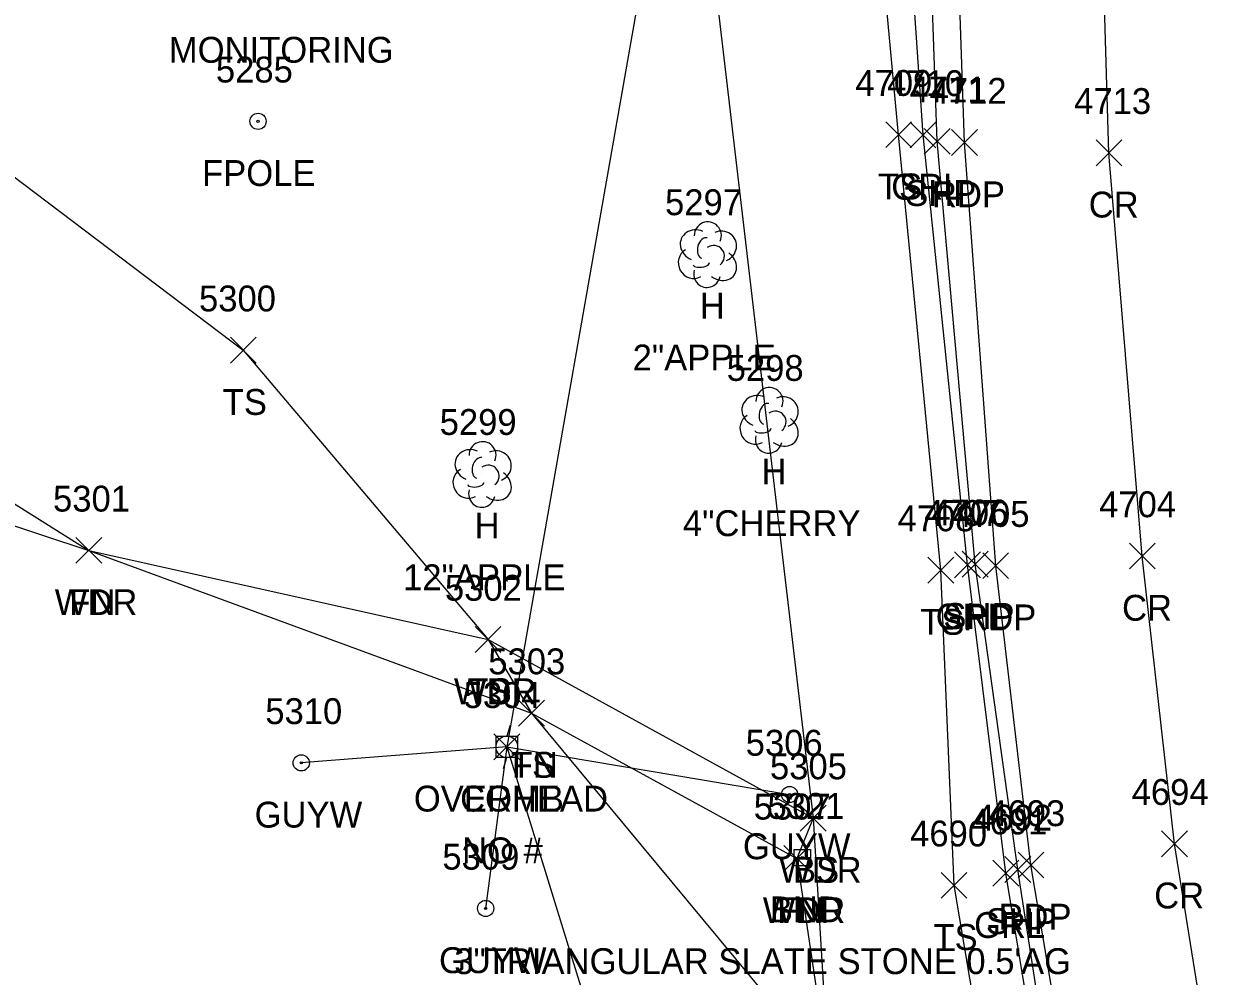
# Model space of a CAD drawing. Extents: x 1601151 to 1602912, y 499508 to 501770.
# Drawn here: x 1601373.9 to 1601465.7, y 501166.3 to 501239.9 of the extents above; entities that cross this region are included whole.
import ezdxf

# ---------------------------------------------------------------- set-up
doc = ezdxf.new("R2010")
doc.units = 0
for name, color, linetype in [('L_A', 7, 'Continuous'), ('L_C', 7, 'Continuous'), ('L_I', 7, 'Continuous'), ('L_TIC', 7, 'Continuous'), ('LAWA', 7, 'Continuous'), ('LELB', 7, 'Continuous'), ('LFNC', 7, 'Continuous'), ('LFP', 7, 'Continuous'), ('LTD', 7, 'Continuous'), ('M_A', 7, 'Continuous'), ('M_C', 7, 'Continuous'), ('M_I', 7, 'Continuous'), ('MHBP', 7, 'Continuous'), ('P_A', 7, 'Continuous'), ('P_I', 7, 'Continuous'), ('P_TIC', 7, 'Continuous'), ('PET', 7, 'Continuous'), ('PRC', 7, 'Continuous'), ('PSP', 7, 'Continuous'), ('R_A', 7, 'Continuous'), ('R_I', 7, 'Continuous'), ('R_TIC', 7, 'Continuous'), ('RGR', 7, 'Continuous'), ('U_A', 7, 'Continuous'), ('U_C', 7, 'Continuous'), ('U_I', 7, 'Continuous'), ('U_TIC', 7, 'Continuous'), ('UCO', 7, 'Continuous'), ('UP', 7, 'Continuous'), ('UPGW', 7, 'Continuous')]:
    doc.layers.add(name, color=color, linetype=linetype)

msp = doc.modelspace()

# ---------------------------------------------------------------- linework, layer by layer
at = {"layer": 'L_TIC'}
for points in [[(1601440.57, 501230.326), (1601442.57, 501232.326)], [(1601442.57, 501230.326), (1601440.57, 501232.326)], [(1601389.909, 501213.668), (1601391.909, 501215.668)], [(1601391.909, 501213.668), (1601389.909, 501215.668)], [(1601377.97, 501198.195), (1601379.97, 501200.195)], [(1601379.97, 501198.195), (1601377.97, 501200.195)], [(1601377.97, 501198.195), (1601379.97, 501200.195)], [(1601379.97, 501198.195), (1601377.97, 501200.195)], [(1601443.83, 501196.671), (1601445.83, 501198.671)], [(1601445.83, 501196.671), (1601443.83, 501198.671)], [(1601408.831, 501191.304), (1601410.831, 501193.304)], [(1601410.831, 501191.304), (1601408.831, 501193.304)], [(1601408.831, 501191.304), (1601410.831, 501193.304)], [(1601410.831, 501191.304), (1601408.831, 501193.304)], [(1601412.186, 501185.617), (1601414.186, 501187.617)], [(1601414.186, 501185.617), (1601412.186, 501187.617)], [(1601412.186, 501185.617), (1601414.186, 501187.617)], [(1601414.186, 501185.617), (1601412.186, 501187.617)], [(1601433.964, 501177.502), (1601435.964, 501179.502)], [(1601435.964, 501177.502), (1601433.964, 501179.502)], [(1601433.964, 501177.502), (1601435.964, 501179.502)], [(1601435.964, 501177.502), (1601433.964, 501179.502)], [(1601432.708, 501174.388), (1601434.708, 501176.388)], [(1601434.708, 501174.388), (1601432.708, 501176.388)], [(1601432.708, 501174.388), (1601434.708, 501176.388)], [(1601434.708, 501174.388), (1601432.708, 501176.388)], [(1601444.853, 501172.31), (1601446.853, 501174.31)], [(1601446.853, 501172.31), (1601444.853, 501174.31)]]:
    msp.add_lwpolyline(points, dxfattribs=at)
at = {"layer": 'LAWA'}
msp.add_lwpolyline([(1601349.444, 501208.947), (1601378.97, 501199.195), (1601409.831, 501192.304), (1601434.964, 501178.502), (1601433.708, 501175.388), (1601436.145, 501158.977), (1601428.329, 501130.739), (1601431.936, 501098.399), (1601430.553, 501050.275), (1601438.297, 501031.991)], dxfattribs=at)
at = {"layer": 'LELB'}
for points in [[(1601519.45, 500871.015), (1601514.106, 500889.305), (1601500.792, 500936.504), (1601490.019, 500979.284), (1601479.001, 501021.428), (1601469.31, 501063.641), (1601460.331, 501100.011), (1601451.952, 501137.211), (1601445.853, 501173.31), (1601444.83, 501197.671), (1601441.57, 501231.326), (1601439.967, 501248.562), (1601437.525, 501260.474), (1601435.288, 501265.518), (1601431.823, 501269.236), (1601423.18, 501278.02), (1601413.06, 501283.538), (1601401.407, 501287.173), (1601388.073, 501289.756), (1601350.994, 501290.93), (1601302.639, 501293.089), (1601266.114, 501297.128)], [(1601265.967, 501291.231), (1601301.347, 501286.944), (1601350.829, 501278.015), (1601381.445, 501274.61), (1601399.659, 501274.5), (1601409.178, 501273.199), (1601415.682, 501262.208), (1601424.82, 501255.747), (1601426.994, 501246.294), (1601434.964, 501178.502), (1601436.145, 501158.977), (1601412.569, 501136.795), (1601410.789, 501093.147), (1601430.553, 501050.275)], [(1601346.341, 501219.667), (1601359.287, 501227.855), (1601371.057, 501229.665), (1601390.909, 501214.668), (1601409.831, 501192.304), (1601413.186, 501186.617), (1601436.145, 501158.977)]]:
    msp.add_lwpolyline(points, dxfattribs=at)
at = {"layer": 'LFNC'}
msp.add_lwpolyline([(1601346.341, 501219.667), (1601378.97, 501199.195), (1601413.186, 501186.617), (1601433.708, 501175.388)], dxfattribs=at)
at = {"layer": 'LFP'}
for radius in [0.625, 0.0833]:
    msp.add_circle((1601392.05, 501232.361), radius, dxfattribs=at)
at = {"layer": 'LTD'}
for p, q in [((1601426.773, 501222.105), (1601426.773, 501222.105)), ((1601426.773, 501222.105), (1601426.773, 501222.105)), ((1601431.54, 501209.297), (1601431.54, 501209.297)), ((1601431.54, 501209.297), (1601431.54, 501209.297)), ((1601409.358, 501205.118), (1601409.358, 501205.118)), ((1601409.358, 501205.118), (1601409.358, 501205.118))]:
    msp.add_line(p, q, dxfattribs=at)
for centre in [(1601426.82, 501223.539), (1601431.587, 501210.731), (1601409.405, 501206.552)]:
    msp.add_arc(centre, 1.047, 335.52715, 180.95627, dxfattribs=at)
for centre, major_axis, ratio, start_param, end_param in [((1601425.981, 501222.772), (1.21, -0.512), 0.895232, 1.570796, 4.712389), ((1601426.565, 501222.564), (-0.208, -0.792), 0.645439, 3.141593, 6.283185), ((1601427.815, 501222.689), (-1.141, -0.483), 0.949671, 1.570796, 4.712389), ((1601425.69, 501221.397), (0.584, -1.042), 0.959034, 3.141593, 6.283185), ((1601427.273, 501221.939), (-0.5, 0.667), 0.989748, 3.141593, 6.283185), ((1601426.315, 501221.355), (-0.625, -0.083), 0.423636, 0, 3.141593), ((1601427.773, 501221.272), (-1.09, 0.792), 0.841452, 1.570796, 4.712389), ((1601426.773, 501220.605), (0.265, 1.061), 0.942809, 1.570796, 4.712389), ((1601430.748, 501209.964), (1.21, -0.512), 0.895232, 1.570796, 4.712389), ((1601432.582, 501209.881), (-1.141, -0.483), 0.949671, 1.570796, 4.712389), ((1601431.332, 501209.756), (-0.208, -0.792), 0.645439, 3.141593, 6.283185), ((1601430.457, 501208.589), (0.584, -1.042), 0.959034, 3.141593, 6.283185), ((1601432.04, 501209.131), (-0.5, 0.667), 0.989748, 3.141593, 6.283185), ((1601432.54, 501208.464), (-1.09, 0.792), 0.841452, 1.570796, 4.712389), ((1601431.082, 501208.547), (-0.625, -0.083), 0.423636, 0, 3.141593), ((1601431.54, 501207.797), (0.265, 1.061), 0.942809, 1.570796, 4.712389), ((1601408.566, 501205.784), (1.21, -0.512), 0.895232, 1.570796, 4.712389), ((1601410.4, 501205.701), (-1.141, -0.483), 0.949671, 1.570796, 4.712389), ((1601409.15, 501205.576), (-0.208, -0.792), 0.645439, 3.141593, 6.283185), ((1601409.858, 501204.951), (-0.5, 0.667), 0.989748, 3.141593, 6.283185), ((1601408.275, 501204.409), (0.584, -1.042), 0.959034, 3.141593, 6.283185), ((1601410.358, 501204.285), (-1.09, 0.792), 0.841452, 1.570796, 4.712389), ((1601408.9, 501204.368), (-0.625, -0.083), 0.423636, 0, 3.141593), ((1601409.359, 501203.618), (0.265, 1.061), 0.942809, 1.570796, 4.712389)]:
    msp.add_ellipse(centre, major_axis=major_axis, ratio=ratio, start_param=start_param, end_param=end_param, dxfattribs=at)
at = {"layer": 'MHBP'}
msp.add_lwpolyline([(1601433.499, 501176.068), (1601434.749, 501176.068), (1601434.749, 501174.818), (1601433.499, 501174.818)], close=True, dxfattribs=at)
msp.add_circle((1601434.124, 501175.443), 0.0833, dxfattribs=at)
at = {"layer": 'P_TIC'}
for points in [[(1601443.544, 501229.817), (1601445.544, 501231.817)], [(1601445.544, 501229.817), (1601443.544, 501231.817)], [(1601445.661, 501229.716), (1601447.661, 501231.716)], [(1601447.661, 501229.716), (1601445.661, 501231.716)], [(1601456.835, 501228.924), (1601458.835, 501230.924)], [(1601458.835, 501228.924), (1601456.835, 501230.924)], [(1601459.41, 501197.758), (1601461.41, 501199.758)], [(1601461.41, 501197.758), (1601459.41, 501199.758)], [(1601446.494, 501197.124), (1601448.494, 501199.124)], [(1601448.494, 501197.124), (1601446.494, 501199.124)], [(1601448.078, 501197.013), (1601450.078, 501199.013)], [(1601450.078, 501197.013), (1601448.078, 501199.013)], [(1601461.895, 501175.52), (1601463.895, 501177.52)], [(1601463.895, 501175.52), (1601461.895, 501177.52)], [(1601449.781, 501173.537), (1601451.781, 501175.537)], [(1601451.781, 501173.537), (1601449.781, 501175.537)], [(1601450.804, 501173.879), (1601452.804, 501175.879)], [(1601452.804, 501173.879), (1601450.804, 501175.879)]]:
    msp.add_lwpolyline(points, dxfattribs=at)
at = {"layer": 'PET'}
msp.add_lwpolyline([(1601523.483, 500870.901), (1601505.835, 500938.639), (1601494.516, 500981.09), (1601483.993, 501022.882), (1601473.436, 501065.013), (1601465.152, 501101.359), (1601457.991, 501138.154), (1601451.804, 501174.879), (1601449.078, 501198.013), (1601446.661, 501230.716), (1601445.888, 501253.394), (1601447.493, 501294.254), (1601451.947, 501334.775), (1601458.706, 501377.25), (1601475.949, 501468.235), (1601495.788, 501558.679), (1601503.764, 501593.609), (1601511.667, 501629.007)], dxfattribs=at)
at = {"layer": 'PRC'}
msp.add_lwpolyline([(1601533.301, 500873.429), (1601528.203, 500892.927), (1601515.881, 500940.69), (1601516.086, 500940.413), (1601505.083, 500982.796), (1601494.066, 501025.459), (1601483.894, 501067.42), (1601475.626, 501103.842), (1601468.616, 501140.875), (1601462.895, 501176.52), (1601460.41, 501198.758), (1601457.835, 501229.924), (1601457.034, 501256.973), (1601458.232, 501305.055), (1601463.89, 501343.749), (1601469.525, 501375.722), (1601487.672, 501465.727), (1601498.93, 501516.839), (1601507.235, 501554.653), (1601515.351, 501591.128), (1601523.432, 501627.297), (1601533.113, 501671.567)], dxfattribs=at)
at = {"layer": 'PSP'}
msp.add_lwpolyline([(1601522.474, 500870.61), (1601521.439, 500871.557), (1601516.681, 500890.315), (1601504.629, 500938.047), (1601493.734, 500980.105), (1601482.813, 501022.433), (1601472.391, 501064.7), (1601463.732, 501101.178), (1601456.463, 501137.785), (1601450.781, 501174.537), (1601447.494, 501198.124), (1601444.544, 501230.817), (1601443.787, 501252.816), (1601439.569, 501267.268), (1601434.996, 501273.885), (1601425.866, 501282.164), (1601414.434, 501288.016), (1601402.059, 501290.613), (1601388.178, 501292.297), (1601350.65, 501293.394), (1601302.631, 501296.391), (1601266.655, 501300.033)], dxfattribs=at)
at = {"layer": 'R_TIC'}
for points in [[(1601442.458, 501230.306), (1601444.458, 501232.306)], [(1601444.458, 501230.306), (1601442.458, 501232.306)], [(1601445.894, 501197.084), (1601447.894, 501199.084)], [(1601447.894, 501197.084), (1601445.894, 501199.084)], [(1601448.863, 501173.239), (1601450.863, 501175.239)], [(1601450.863, 501173.239), (1601448.863, 501175.239)]]:
    msp.add_lwpolyline(points, dxfattribs=at)
at = {"layer": 'RGR'}
msp.add_lwpolyline([(1601521.194, 500871.519), (1601516.168, 500890.132), (1601503.522, 500937.626), (1601493.244, 500980.032), (1601482.37, 501022.092), (1601471.561, 501064.484), (1601463.235, 501100.712), (1601455.926, 501137.469), (1601449.863, 501174.239), (1601446.894, 501198.084), (1601443.458, 501231.306), (1601442.272, 501248.597), (1601440.181, 501261.029), (1601437.509, 501266.718), (1601434.074, 501271.664), (1601424.696, 501280.104), (1601413.846, 501286.207), (1601401.696, 501289.169), (1601388.073, 501289.756)], dxfattribs=at)
at = {"layer": 'U_TIC'}
for points in [[(1601410.283, 501183.01), (1601412.283, 501185.01)], [(1601412.283, 501183.01), (1601410.283, 501185.01)]]:
    msp.add_lwpolyline(points, dxfattribs=at)
at = {"layer": 'UCO'}
msp.add_lwpolyline([(1601766.645, 501489.445), (1601471.02, 501503.898), (1601438.705, 501339.971), (1601411.283, 501184.01), (1601489.931, 500928.889)], dxfattribs=at)
at = {"layer": 'UP'}
for p, q in [((1601411.533, 501185.677), (1601411.283, 501184.843)), ((1601410.45, 501183.177), (1601410.45, 501184.843)), ((1601410.45, 501184.843), (1601412.116, 501184.843)), ((1601412.116, 501184.843), (1601412.116, 501183.177)), ((1601411.283, 501184.01), (1601411.283, 501184.01)), ((1601412.116, 501183.177), (1601410.45, 501183.177)), ((1601411.033, 501182.343), (1601411.283, 501183.177))]:
    msp.add_line(p, q, dxfattribs=at)
msp.add_circle((1601411.283, 501184.01), 0.833, dxfattribs=at)
at = {"layer": 'UPGW'}
for points in [[(1601411.283, 501184.01), (1601395.389, 501182.77)], [(1601411.283, 501184.01), (1601409.644, 501171.52)], [(1601411.283, 501184.01), (1601433.142, 501180.325)]]:
    msp.add_lwpolyline(points, dxfattribs=at)
for centre, radius in [((1601395.389, 501182.77), 0.625), ((1601395.389, 501182.77), 0.0833), ((1601433.142, 501180.325), 0.625), ((1601433.142, 501180.325), 0.0833), ((1601409.644, 501171.52), 0.625), ((1601409.644, 501171.52), 0.0833)]:
    msp.add_circle(centre, radius, dxfattribs=at)

# ---------------------------------------------------------------- texts
at = {"layer": 'L_A'}
for s, p in [('FPOLE', (1601387.719, 501227.361)), ('TS', (1601439.979, 501226.326)), ('H', (1601426.206, 501217.105)), ('TS', (1601389.318, 501209.668)), ('H', (1601430.973, 501204.297)), ('H', (1601408.791, 501200.118)), ('WDR', (1601376.332, 501194.195)), ('FN', (1601377.45, 501194.195)), ('TS', (1601443.24, 501192.671)), ('WDR', (1601407.193, 501187.304)), ('TS', (1601408.241, 501187.304)), ('TS', (1601411.595, 501181.617)), ('FN', (1601411.666, 501181.617)), ('WDR', (1601432.326, 501173.502)), ('BS', (1601433.405, 501173.502)), ('WDR', (1601431.07, 501170.388)), ('FN', (1601432.188, 501170.388)), ('TS', (1601444.263, 501168.31))]:
    msp.add_text(s, height=2, dxfattribs=at).set_placement(p)
at = {"layer": 'L_C'}
for s, p in [('2"APPLE', (1601421.01, 501213.105)), ('4"CHERRY', (1601424.895, 501200.297)), ('12"APPLE', (1601403.264, 501196.118))]:
    msp.add_text(s, height=2, dxfattribs=at).set_placement(p)
at = {"layer": 'L_I'}
for s, p in [('5285', (1601388.79, 501235.361)), ('4709', (1601438.224, 501234.326)), ('5297', (1601423.513, 501225.105)), ('5300', (1601387.484, 501217.668)), ('5298', (1601428.28, 501212.297)), ('5299', (1601406.091, 501208.118)), ('5301', (1601376.199, 501202.195)), ('5301', (1601376.199, 501202.195)), ('4708', (1601441.492, 501200.671)), ('5302', (1601406.493, 501195.304)), ('5302', (1601406.493, 501195.304)), ('5303', (1601409.847, 501189.617)), ('5303', (1601409.847, 501189.617)), ('5305', (1601431.625, 501181.502)), ('5305', (1601431.625, 501181.502)), ('5307', (1601430.369, 501178.388)), ('5307', (1601430.369, 501178.388)), ('4690', (1601442.46, 501176.31))]:
    msp.add_text(s, height=2, dxfattribs=at).set_placement(p)
at = {"layer": 'M_A'}
msp.add_text('BND', height=2, dxfattribs=at).set_placement((1601431.612, 501170.443))
at = {"layer": 'M_C'}
msp.add_text('3"TRIANGULAR SLATE STONE 0.5\'AG', height=2, dxfattribs=at).set_placement((1601407.219, 501166.443))
at = {"layer": 'M_I'}
msp.add_text('5321', height=2, dxfattribs=at).set_placement((1601431.431, 501178.443))
at = {"layer": 'P_A'}
for s, p in [('SHP', (1601442.08, 501225.817)), ('RDP', (1601444.149, 501225.716)), ('CR', (1601456.268, 501224.924)), ('CR', (1601458.843, 501193.758)), ('SHP', (1601445.029, 501193.124)), ('RDP', (1601446.566, 501193.013)), ('CR', (1601461.328, 501171.52)), ('RDP', (1601449.292, 501169.879)), ('SHP', (1601448.316, 501169.537))]:
    msp.add_text(s, height=2, dxfattribs=at).set_placement(p)
at = {"layer": 'P_I'}
for s, p in [('4711', (1601442.418, 501233.817)), ('4712', (1601443.968, 501233.716)), ('4713', (1601455.142, 501232.924)), ('4706', (1601444.1, 501201.124)), ('4705', (1601445.74, 501201.013)), ('4704', (1601457.071, 501201.758)), ('4694', (1601459.588, 501179.52)), ('4692', (1601447.474, 501177.537)), ('4693', (1601448.497, 501177.879))]:
    msp.add_text(s, height=2, dxfattribs=at).set_placement(p)
at = {"layer": 'R_A'}
for p in [(1601441.001, 501226.306), (1601444.438, 501193.084), (1601447.406, 501169.239)]:
    msp.add_text('GRL', height=2, dxfattribs=at).set_placement(p)
at = {"layer": 'R_I'}
for s, p in [('4710', (1601440.679, 501234.306)), ('4707', (1601443.556, 501201.084)), ('4691', (1601447.123, 501177.239))]:
    msp.add_text(s, height=2, dxfattribs=at).set_placement(p)
at = {"layer": 'U_A'}
for s, p in [('OVERHEAD', (1601404.094, 501179.01)), ('COMB', (1601407.669, 501179.01)), ('GUYW', (1601391.783, 501177.77)), ('GUYW', (1601429.535, 501175.325)), ('GUYW', (1601406.038, 501166.52))]:
    msp.add_text(s, height=2, dxfattribs=at).set_placement(p)
at = {"layer": 'U_C'}
for s, p in [('MONITORING', (1601385.153, 501236.888)), ('NO #', (1601407.818, 501175.01))]:
    msp.add_text(s, height=2, dxfattribs=at).set_placement(p)
at = {"layer": 'U_I'}
for s, p in [('5304', (1601407.944, 501187.01)), ('5304', (1601407.944, 501187.01)), ('5310', (1601392.61, 501185.77)), ('5306', (1601429.748, 501183.325)), ('5309', (1601406.298, 501174.52))]:
    msp.add_text(s, height=2, dxfattribs=at).set_placement(p)

doc.saveas('drawing.dxf')
